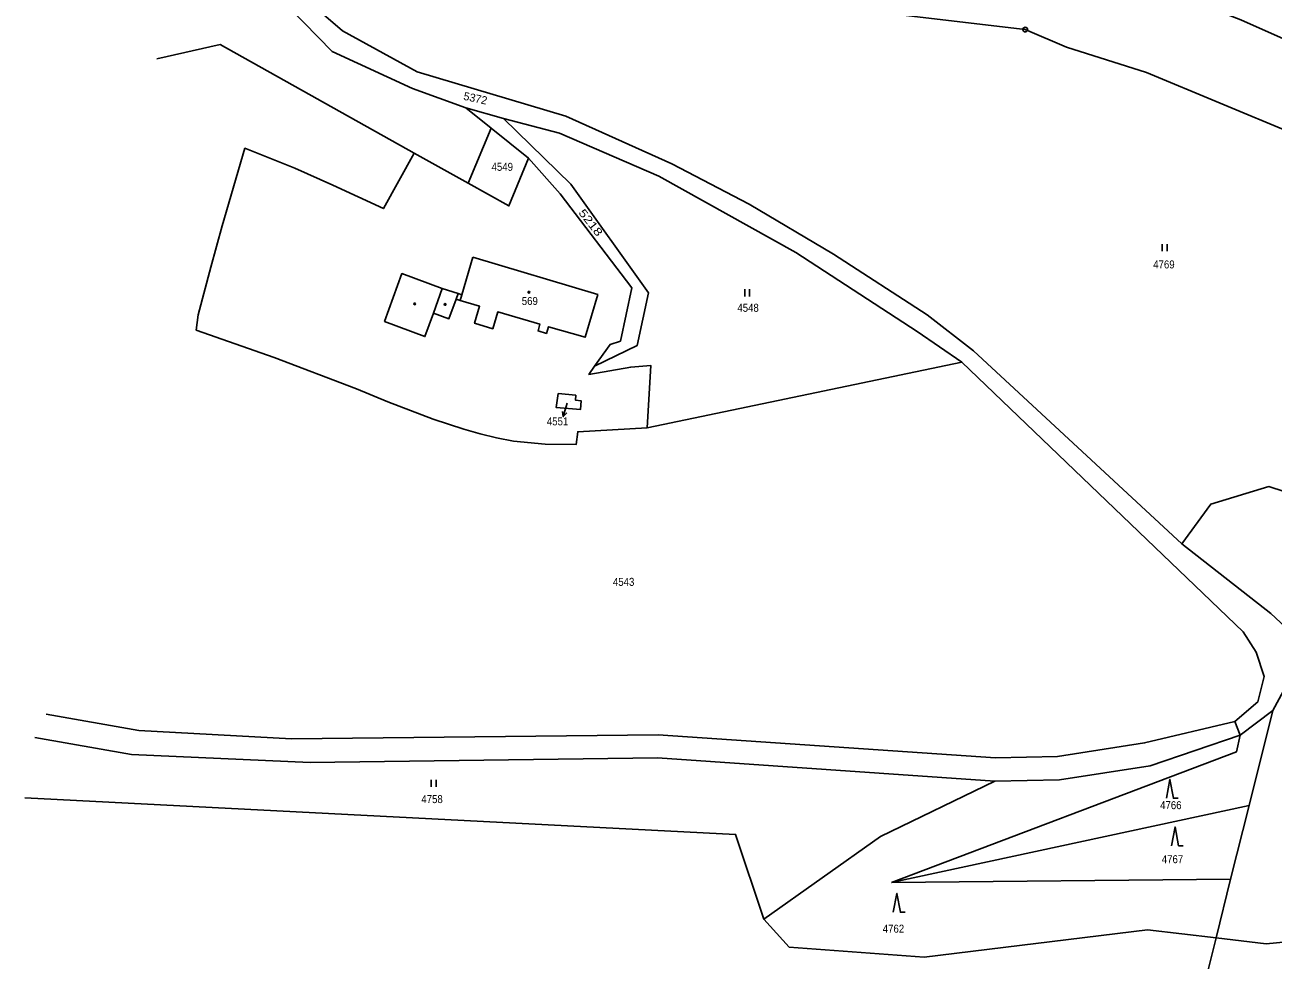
# Model space of a CAD drawing. Extents: x -665688 to -664583, y -1006118 to -1004927.
# Drawn here: x -665675.6 to -665410.4, y -1005400.3 to -1005201.6 of the extents above; entities that cross this region are included whole.
import ezdxf
from ezdxf.enums import TextEntityAlignment as Align

# ---------------------------------------------------------------- set-up
doc = ezdxf.new("R2010")
doc.units = 0
doc.header["$LTSCALE"] = 0.68
for name, color, linetype, lineweight in [('1', 7, 'Continuous', 25), ('16', 7, 'Continuous', 25), ('24', 7, 'Continuous', 25), ('25', 7, 'Continuous', 25), ('4', 7, 'Continuous', 25)]:
    doc.layers.add(name, color=color, linetype=linetype, lineweight=lineweight)
doc.layers.add('18', color=7, linetype='Continuous')
doc.layers.add('19', color=7, linetype='Continuous')

msp = doc.modelspace()

# ---------------------------------------------------------------- linework, layer by layer
at = {"layer": '1'}
for p, q in [((-665581.94, -1005219.27), (-665573.97, -1005221.52)), ((-665417.41, -1005352.55), (-665418.54, -1005349.65)), ((-665491.5, -1005383.82), (-665419.44, -1005383.17)), ((-665434.55, -1005443.84), (-665422.54, -1005395.61))]:
    msp.add_line(p, q, dxfattribs=at)
for points in [[(-665593.42, -1005154.98), (-665590.17, -1005156.55), (-665581.14, -1005160.82), (-665545.66, -1005172.05), (-665527.86, -1005181.07), (-665527.45, -1005180.2), (-665515.99, -1005181.03), (-665490.32, -1005183.42), (-665458.39, -1005187.75), (-665437.98, -1005192.49), (-665417.3, -1005200.53), (-665399.75, -1005208.35)], [(-665637.59, -1005176.03), (-665619.42, -1005197.98), (-665610.34, -1005207.28), (-665593.31, -1005215.14), (-665581.94, -1005219.27)], [(-665429.85, -1005311.87), (-665474.09, -1005270.9), (-665483.93, -1005263.19), (-665503.85, -1005250.35), (-665521.76, -1005239.72), (-665538.2, -1005231.14), (-665560.7, -1005220.99), (-665592.26, -1005211.56), (-665608.15, -1005202.85), (-665616.64, -1005195.48), (-665630.18, -1005176.74)], [(-665606.44, -1005185.69), (-665588.29, -1005189.45), (-665568.47, -1005193.44), (-665524.68, -1005197.88), (-665491.46, -1005199.28), (-665463.07, -1005202.62), (-665454.32, -1005206.34), (-665437.29, -1005211.76), (-665406.05, -1005224.73)], [(-665592.9, -1005228.86), (-665634.14, -1005205.81), (-665647.62, -1005208.8)], [(-665554.64, -1005274.1), (-665551.31, -1005269.52), (-665549.09, -1005268.81), (-665546.66, -1005257.48), (-665561.91, -1005237.53), (-665568.61, -1005229.93), (-665576.58, -1005223.55), (-665581.94, -1005219.27)], [(-665576.58, -1005223.55), (-665581.43, -1005235.27), (-665592.9, -1005228.86)], [(-665573.97, -1005221.52), (-665562.06, -1005224.65), (-665540.95, -1005233.73), (-665511.85, -1005249.99), (-665486.07, -1005266.77), (-665476.53, -1005273.29), (-665543.41, -1005287.27)], [(-665573.97, -1005221.52), (-665559.62, -1005235.47), (-665543.13, -1005258.55), (-665545.55, -1005269.76), (-665554.64, -1005274.1)], [(-665592.9, -1005228.86), (-665599.48, -1005240.64), (-665610.23, -1005235.64), (-665618.28, -1005232.09), (-665628.88, -1005227.82), (-665633.71, -1005244.3), (-665636.11, -1005253.11), (-665638.85, -1005263.2), (-665639.23, -1005266.45)], [(-665581.43, -1005235.27), (-665572.81, -1005240.08), (-665568.61, -1005229.93)], [(-665580.45, -1005250.95), (-665582.8, -1005258.99), (-665583.61, -1005258.72), (-665586.96, -1005257.62)], [(-665583.15, -1005260.2), (-665579.04, -1005261.41), (-665580.1, -1005265.02), (-665576.24, -1005266.18), (-665575.18, -1005262.6), (-665566.2, -1005265.22), (-665566.6, -1005266.65), (-665564.83, -1005267.18), (-665564.42, -1005265.74), (-665556.62, -1005268), (-665553.92, -1005258.91), (-665580.45, -1005250.95)], [(-665586.96, -1005257.62), (-665595.53, -1005254.46), (-665599.21, -1005264.63), (-665590.66, -1005267.86), (-665588.79, -1005262.84)], [(-665429.85, -1005311.87), (-665423.66, -1005303.48), (-665411.3, -1005299.73), (-665386.72, -1005307.69), (-665378.56, -1005308.54), (-665363.85, -1005302.58), (-665350.44, -1005303.75), (-665338.78, -1005316.57), (-665316.9, -1005318.19), (-665319.2, -1005305.57), (-665355.41, -1005256.31)], [(-665588.79, -1005262.84), (-665585.53, -1005264.05), (-665584.04, -1005259.93), (-665583.15, -1005260.2)], [(-665543.41, -1005287.27), (-665558.17, -1005288.07), (-665558.48, -1005290.75), (-665565.11, -1005290.71), (-665571.84, -1005290.04), (-665575.41, -1005289.37), (-665578.91, -1005288.53), (-665582.37, -1005287.55), (-665588.86, -1005285.37), (-665598.55, -1005281.68), (-665605.19, -1005278.96), (-665622.67, -1005272.28), (-665639.23, -1005266.45)], [(-665543.41, -1005287.27), (-665542.67, -1005273.99), (-665546.92, -1005274.31), (-665555.8, -1005275.9), (-665554.64, -1005274.1)], [(-665476.53, -1005273.29), (-665416.78, -1005330.59), (-665414.05, -1005334.93), (-665412.3, -1005340.08), (-665413.7, -1005345.48), (-665418.54, -1005349.65)], [(-665410.5, -1005347.29), (-665408.21, -1005343.15), (-665405.83, -1005331.43), (-665410.87, -1005326.68), (-665429.85, -1005311.87)], [(-665418.54, -1005349.65), (-665437.74, -1005354.19), (-665456.23, -1005357.06), (-665469.44, -1005357.33), (-665541.08, -1005352.51), (-665619.02, -1005353.3), (-665651.44, -1005351.55), (-665671.13, -1005348.1)], [(-665410.5, -1005347.29), (-665415.52, -1005367.46), (-665491.5, -1005383.82)], [(-665491.5, -1005383.82), (-665418.18, -1005356.07), (-665417.41, -1005352.55), (-665410.5, -1005347.29)], [(-665673.52, -1005353.03), (-665653.02, -1005356.63), (-665615.02, -1005358.34), (-665541.24, -1005357.38), (-665469.56, -1005362.34)], [(-665469.56, -1005362.34), (-665455.79, -1005362.05), (-665436.54, -1005359.07), (-665417.41, -1005352.55)], [(-665518.63, -1005391.67), (-665493.85, -1005374.11), (-665469.56, -1005362.34)], [(-665675.63, -1005365.85), (-665524.62, -1005373.63), (-665518.63, -1005391.67)], [(-665422.54, -1005395.61), (-665419.44, -1005383.17), (-665415.52, -1005367.46)], [(-665422.54, -1005395.61), (-665411.87, -1005396.87), (-665331.44, -1005389.13), (-665257.43, -1005376.61), (-665238, -1005377.08)], [(-665518.63, -1005391.67), (-665513.24, -1005397.63), (-665484.6, -1005399.69), (-665437.08, -1005393.91), (-665422.54, -1005395.61)]]:
    msp.add_lwpolyline(points, dxfattribs=at)
msp.add_lwpolyline([(-665562.33, -1005279.95), (-665558.59, -1005280.31), (-665558.64, -1005281.37), (-665557.43, -1005281.53), (-665557.61, -1005283.35), (-665562.75, -1005282.95)], close=True, dxfattribs=at)
at = {"layer": '16'}
msp.add_line((-665560.39, -1005281.98), (-665561.247, -1005284.854), dxfattribs=at)
msp.add_lwpolyline([(-665560.482, -1005284.039), (-665561.247, -1005284.854), (-665561.44, -1005283.753)], dxfattribs=at)
at = {"layer": '24'}
for radius in [0.5, 0.032]:
    msp.add_circle((-665463.07, -1005202.62), radius, dxfattribs=at)
at = {"layer": '25'}
for p, q in [((-665433.987, -1005249.685), (-665433.987, -1005248.185)), ((-665432.953, -1005249.685), (-665432.953, -1005248.185)), ((-665522.697, -1005259.305), (-665522.697, -1005257.805)), ((-665521.663, -1005259.305), (-665521.663, -1005257.805)), ((-665589.297, -1005363.515), (-665589.297, -1005362.015)), ((-665588.263, -1005363.515), (-665588.263, -1005362.015))]:
    msp.add_line(p, q, dxfattribs=at)
for points in [[(-665433.1, -1005365.95), (-665432.35, -1005361.95), (-665431.6, -1005365.95), (-665430.6, -1005365.95)], [(-665432, -1005376.05), (-665431.25, -1005372.05), (-665430.5, -1005376.05), (-665429.5, -1005376.05)], [(-665491.12, -1005390.19), (-665490.37, -1005386.19), (-665489.62, -1005390.19), (-665488.62, -1005390.19)]]:
    msp.add_lwpolyline(points, dxfattribs=at)
for centre in [(-665568.56, -1005258.41), (-665592.84, -1005260.9), (-665586.35, -1005261.02)]:
    msp.add_circle(centre, 0.175, dxfattribs=at)
at = {"layer": '4'}
for p, q in [((-665588.79, -1005262.84), (-665586.96, -1005257.62)), ((-665584.04, -1005259.93), (-665583.61, -1005258.72)), ((-665583.15, -1005260.2), (-665582.8, -1005258.99))]:
    msp.add_line(p, q, dxfattribs=at)

# ---------------------------------------------------------------- texts
at = {"layer": '16', "width": 0.9}
msp.add_text('4551', height=1.7, dxfattribs=at).set_placement((-665562.4595, -1005286.71), align=Align.CENTER)
at = {"layer": '18'}
msp.add_text('5372', height=1.7, rotation=347.803, dxfattribs=at).set_placement((-665580.0931, -1005218.0374), align=Align.CENTER)
at = {"layer": '18', "width": 0.9}
for s, p in [('4549', (-665574.2095, -1005232.62)), ('4769', (-665433.6195, -1005253.36)), ('4548', (-665521.9795, -1005262.58)), ('4543', (-665548.4195, -1005320.82)), ('4758', (-665589.1295, -1005366.98)), ('4766', (-665432.1495, -1005368.27)), ('4767', (-665431.7995, -1005379.75)), ('4762', (-665491.0895, -1005394.52))]:
    msp.add_text(s, height=1.7, dxfattribs=at).set_placement(p, align=Align.CENTER)
at = {"layer": '18', "width": 1.3}
msp.add_text('5218', height=1.7, rotation=308.102, dxfattribs=at).set_placement((-665556.0891, -1005244.1465), align=Align.CENTER)
at = {"layer": '18', "width": 0.9}
msp.add_text('4551', height=0.1, dxfattribs=at).set_placement((-665559.82, -1005281.78))
at = {"layer": '19', "width": 0.9}
msp.add_text('569', height=1.7, dxfattribs=at).set_placement((-665568.3595, -1005261.13), align=Align.CENTER)

doc.saveas('drawing.dxf')
